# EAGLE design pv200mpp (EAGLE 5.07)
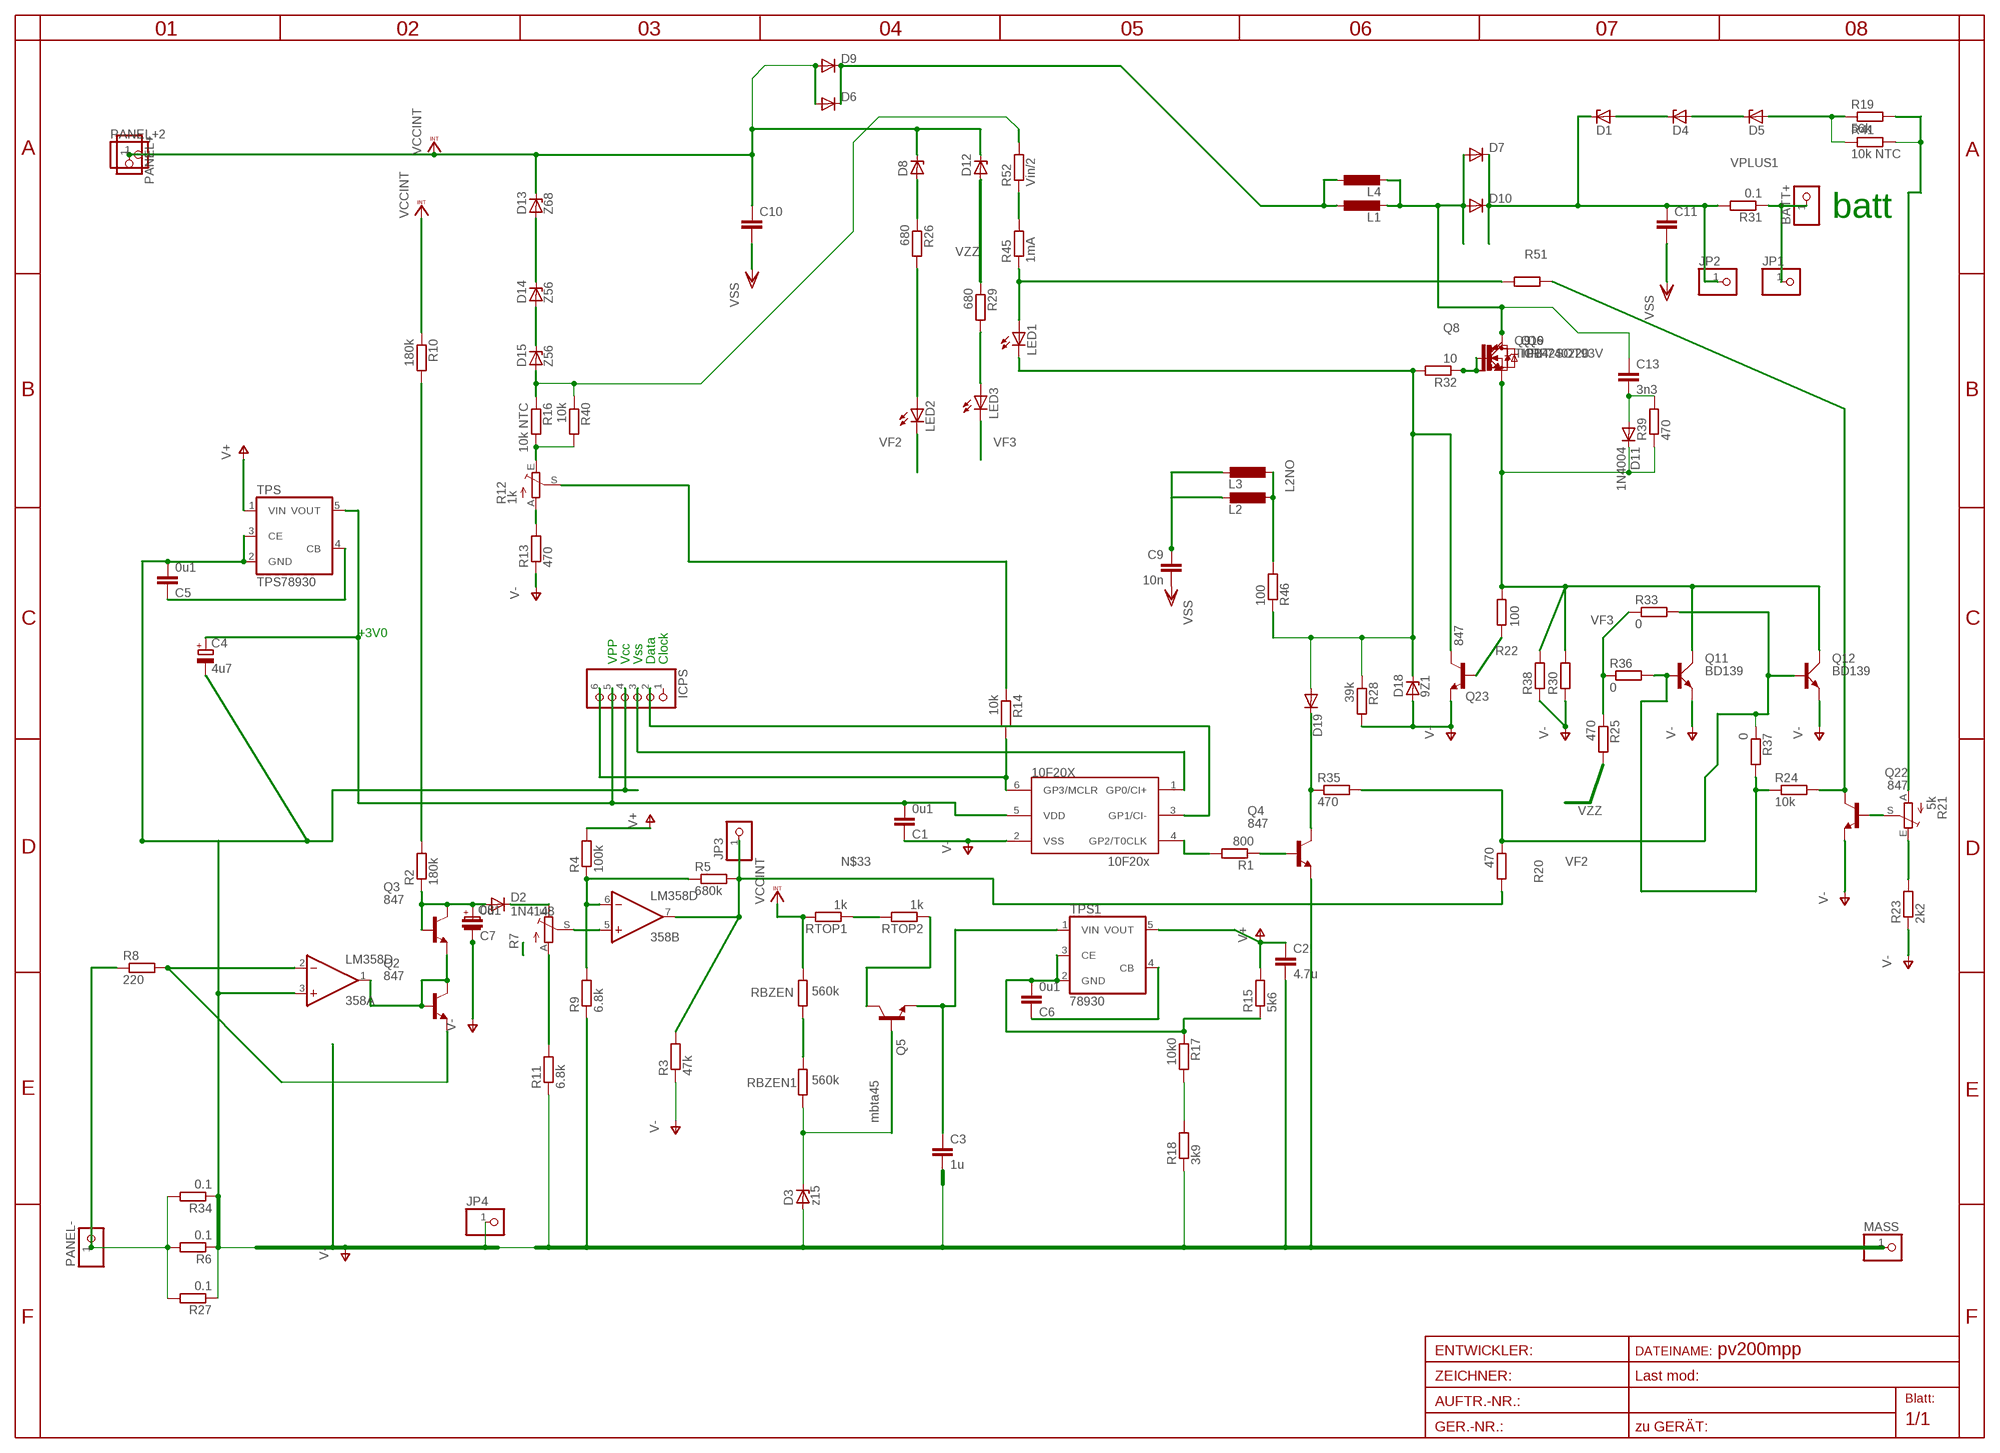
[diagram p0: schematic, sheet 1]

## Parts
10F20X  10F20x  PIC10F204OT  [SOT23-6]
358  LM358D  [SO08]
BATT+  PINHD-1X12MM3  [1X2MM3]
C1  0u1  C-EUC1206  [C1206]
C2  4.7u  C-EUC1206  [C1206]
C3  1u  C-EUC1206  [C1206]
C4  4u7  CPOL-EUSMCA  [SMC_A]
C5  0u1  C-EUC0805  [C0805]
C6  0u1  C-EUC0805  [C0805]
C7  0u1  C-EUC1608  [C1608]
C8  CPOL-EUSMCA  [SMC_A]
C9  10n  C-EUC0805  [C0805]
C10  C-EU075-052X106  [C075-052X106]
C11  C-EU075-052X106  [C075-052X106]
C13  3n3  C-EU050-025X075  [C050-025X075]
D1  ZENER-DIODESOD80C  [SOD80C]
D2  1N4148  DIODE-SOD80C  [SOD80C]
D3  z15  ZENER-DIODESOD80C  [SOD80C]
D4  ZENER-DIODESOD80C  [SOD80C]
D5  ZENER-DIODESOD80C  [SOD80C]
D6  DIODE-SMC  [SMC]
D7  DIODE-SMC  [SMC]
D8  ZENER-DIODESOD80C  [SOD80C]
D9  DIODE-SMC  [SMC]
D10  DIODE-SMC  [SMC]
D11  1N4004  [DO41-10]
D12  ZENER-DIODESOD80C  [SOD80C]
D13  Z68  ZENER-DIODESOD80C  [SOD80C]
D14  Z56  ZENER-DIODESOD80C  [SOD80C]
D15  Z56  ZENER-DIODESOD80C  [SOD80C]
D18  9Z1  ZENER-DIODESOD80C  [SOD80C]
D19  DIODE-MINIMELF  [MINIMELF]
ICPS  PINHD-1X6  [1X06BOX]
JP1  PINHD-1X11MM0  [1X1MM0]
JP2  PINHD-1X11MM0  [1X1MM0]
JP3  PINHD-1X11MM0  [1X1MM0]
JP4  PINHD-1X11MM6  [1X1MM8]
L1  L-EUOPEN6  [OPEN6_3]
L2  L-EUOPEN6  [OPEN6_3]
L3  L-EU0207/12  [0207/12]
L4  L-EU0207/12  [0207/12]
LED1  LEDCHIPLED_1206  [CHIPLED_1206]
LED2  LEDCHIPLED_1206  [CHIPLED_1206]
LED3  LEDCHIPLED_1206  [CHIPLED_1206]
MASS  PINHD-1X12MM3  [1X2MM3]
PANEL+  PINHD-1X11MM0  [1X1MM0]
PANEL+2  PINHD-1X12MM3  [1X2MM3]
PANEL-  PINHD-1X12MM3  [1X2MM3]
Q2  847  BC847ALT1SMD  [SOT23]
Q3  847  BC847ALT1SMD  [SOT23]
Q4  847  BC847ALT1SMD  [SOT23]
Q5  mbta45  BC847ALT1SMD  [SOT23]
Q6  IRF740220  [TO220BV]
Q8  IRG4BC15UD-S  [D2PACK]
Q9  TIP142SOT93V  [SOT93V]
Q11  BD139  [TO126AV]
Q12  BD139  [TO126AV]
Q19  IGBT  N-HEXFET_DPAK-  [TO252]
Q22  847  BC847ASMD  [SOT23]
Q23  847  BC847ASMD  [SOT23]
R1  800  R-EU_R0805  [R0805]
R2  180k  R-EU_0207/15  [0207/15]
R3  47k  R-EU_R0805  [R0805]
R4  100k  R-EU_R1206  [R1206]
R5  680k  R-EU_R0805  [R0805]
R6  0.1  R-EU_R1210  [R1210]
R7  TRIM_EU-S64W  [S64W]
R8  220  R-EU_R0805  [R0805]
R9  6.8k  R-EU_R1206  [R1206]
R10  180k  R-EU_R1206  [R1206]
R11  6.8k  R-EU_R0805  [R0805]
R12  1k  TRIM_EU-S64W  [S64W]
R13  470  R-EU_R0805  [R0805]
R14  10k  R-EU_R0805  [R0805]
R15  5k6  R-EU_R0805  [R0805]
R16  10k NTC  R-EU_0204/2V  [0204V]
R17  10k0  R-EU_R0805  [R0805]
R18  3k9  R-EU_R0805  [R0805]
R19  56k  R-EU_R0805  [R0805]
R20  470  R-EU_R0805  [R0805]
R21  5k  TRIM_EU-S64W  [S64W]
R22  100  R-EU_R0805  [R0805]
R23  2k2  R-EU_R0805  [R0805]
R24  10k  R-EU_R0805  [R0805]
R25  470  R-EU_R1206  [R1206]
R26  680  R-EU_R0805  [R0805]
R27  0.1  R-EU_R3216  [R3216]
R28  39k  R-EU_R0805  [R0805]
R29  680  R-EU_R0805  [R0805]
R30  R-EU_R1210  [R1210]
R31  0.1  R-EU_R1210  [R1210]
R32  10  R-EU_R0805  [R0805]
R33  0  R-EU_R0603  [R0603]
R34  0.1  R-EU_R1210  [R1210]
R35  470  R-EU_R0805  [R0805]
R36  0  R-EU_R0603  [R0603]
R37  0  R-EU_R1206  [R1206]
R38  R-EU_R3216  [R3216]
R39  470  R-EU_0207/10  [0207/10]
R40  10k  R-EU_R0805  [R0805]
R41  10k NTC  R-EU_0204/2V  [0204V]
R45  1mA  R-EU_R1206  [R1206]
R46  100  R-EU_R0805  [R0805]
R51  39k  R-EU_R1206  [R1206]
R52  Vin/2  R-EU_R0805  [R0805]
RBZEN  560k  R-EU_R1206  [R1206]
RBZEN1  560k  R-EU_R1206  [R1206]
RTOP1  1k  R-EU_R1206  [R1206]
RTOP2  1k  R-EU_R1206  [R1206]
TPS  TPS78930  TPS78930SOT23-5  [SOT25]
TPS1  78930  TPS78930SOT23-5  [SOT25]

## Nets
BOOST_EN: D19.C Q4.3(C) R35.1
CB: D3.C Q5.1(B) RBZEN1.2
D1: C13.1 D7.A D10.A L1.2 L4.2 Q6.D Q8.2(C) Q9.C Q19.3(D)
GND1: C6.1 TPS1.4(CB)
IN-: PANEL-.1 R6.2 R8.1 R27.2 R34.2
L1NO: D6.C D9.C L1.1 L4.1
L2DOT: C9.1 L2.2 L3.2
L2NO: L2.1 L3.1 R46.2
N$1: Q11.B R24.1 R36.2 R37.2
N$2: R7.A R11.2
N$3: LED2.A R26.2
N$4: 10F20X.1(GP0/CI+) ICPS.3
N$5: 10F20X.4(GP2/T0CLK) R1.2
N$6: R2.2 R10.2
N$7: 358.1(A:OUT) Q2.1(B) Q2.3(C) Q3.2(E)
N$8: 10F20X.3(GP1/CI-) ICPS.2
N$9: 10F20X.5(VDD) C1.2 C4.+ ICPS.5 TPS.5(VOUT)
N$10: 358.2(A:-IN) Q2.2(E) R8.2
N$11: C5.1 TPS.4(CB)
N$12: C7.2 C8.+ D2.A Q3.1(B) Q3.3(C) R2.1
N$13: D2.C R7.E
N$15: 358.5(B:+IN) R7.S
N$16: Q5.3(C) RTOP2.1
N$17: 358.6(B:-IN) R4.1 R5.1 R9.2
N$18: D15.A R16.1 R40.1 R52.2
N$19: RBZEN1.1 RBZEN.2
N$20: LED1.A R45.1 R51.1
N$21: Q23.1(B) R22.2
N$22: D5.A R19.1 R41.1
N$23: D14.A D15.C
N$24: D13.A D14.C
N$25: R12.E R16.2 R40.2
N$26: R12.A R13.2
N$27: R45.2 R52.1
N$28: R17.2 R18.2
N$29: RTOP1.1 RTOP2.2
N$30: D4.A D5.C
N$31: D1.A D4.C
N$32: R19.2 R21.A R41.2
N$33: 358.7(B:OUT) JP3.1 R3.2 R5.2 R20.2
N$34: R21.E R23.2
N$37: D8.A R26.1
N$38: LED3.A R29.2
N$39: Q4.1(B) R1.1
N$58: Q6.G Q8.1(G) Q9.B Q19.1(G) R32.1
N$71: Q22.3(C) R24.2 R51.2
OUT+: BATT+.1 JP1.1 R31.1
P-: D11.C Q6.S Q8.3(E) Q9.E Q11.C Q12.C Q19.2(S) R22.1 R30.2 R38.2 R39.1
PGATE: D18.C D19.A LED1.C Q23.3(C) R28.1 R32.2 R46.1
PIR: 10F20X.6(GP3/MCLR) ICPS.6 R14.2
PRB1: Q22.1(B) R21.S
SNUB1: C13.2 D11.A R39.2
V15: C3.1 Q5.2(E) TPS1.1(VIN)
V+: C2.1 R4.2 R15.2 TPS1.5(VOUT) TPS.1(VIN)
V-: 10F20X.2(VSS) 358.3(A:+IN) C1.1 C2.2 C3.2 C4.- C5.2 C7.1 C8.- C9.2 C10.2 C11.2 D3.A D18.A ICPS.4 JP4.1 MASS.1 Q4.2(E) Q11.E Q12.E Q22.2(E) Q23.2(E) R3.1 R6.1 R9.1 R11.1 R13.1 R18.1 R23.1 R27.1 R28.2 R30.1 R34.1 R38.1 TPS.2(GND) TPS.3(CE) ; supply symbol labelled VSS
VCCINT: C10.1 D6.A D8.C D9.A D12.C D13.C PANEL+2.1 PANEL+.1 R10.1 RBZEN.1 RTOP1.2
VF2: LED2.C Q12.B R20.1 R33.2 R35.2 R37.1
VF3: LED3.C R25.1 R33.1 R36.1
VINFB: R12.S R14.1
VPLUS1: C11.1 D1.C D7.C D10.C JP2.1 R31.2
VZZ: D12.A R25.2 R29.1
X: C6.2 R15.1 R17.1 TPS1.2(GND) TPS1.3(CE)
Unconnected: ICPS.1

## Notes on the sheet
- batt
- +3V0
- VPP | Vcc | Vss | Data | Clock

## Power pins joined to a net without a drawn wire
V+: 358.8(P:V+)
V-: 358.4(P:V-)

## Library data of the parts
10F20X = microchip-3:PIC10F2*: uPC nW 0,25/0,5k Program Flash memory Comparator
358 = linear:LM358: OP AMP also LM158; LM258; LM2904 Source: http://cache.national.com/ds/LM/LM158.pdf
BATT+ JP1-JP4 MASS PANEL+ PANEL+2 PANEL- = pinhead:PINHD-1X1: PIN HEADER
C1-C3 C5-C7 C9-C11 = rcl:C-EU: CAPACITOR, European symbol
C4 = rcl(2):CPOL-EU: POLARIZED CAPACITOR, European symbol
C8 = rcl:CPOL-EU: POLARIZED CAPACITOR, European symbol
C13 = rcl-2:C-EU: CAPACITOR, European symbol
D1 D3-D5 D8 D12-D15 D18 = diode:ZENER-DIODE: Z-Diode
D2 D6 D7 D9 D10 D19 = diode:DIODE-: DIODE
D11 = diode:1N4004: DIODE
ICPS = pinhead:PINHD-1X6: PIN HEADER
L1-L4 = rcl:L-EU: INDUCTOR, European symbol
LED1-LED3 = led:LED: LED
Q2-Q5 Q22 Q23 = transistor-npn:BC847*: NPN Transistor
Q6 = transistor-power:IRF740: N-CHANNEL MOS FET
Q8 = transistor-power:IRG4BC15UD-: INSULATED GATE BIPOLAR TRANSISTOR WITH ULTRAFAST SOFT RECOVERY DIODE
Q9 = transistor-power:TIP142: NPN DARLINGTON TRANSISTOR
Q11 Q12 = transistor-power:BD139: NPN TRANSISTOR
Q19 = transistor-power:N-HEXFET_?-*: HEXFET® Power MOSFET
R1-R6 R8-R11 R13-R20 R22-R31 R33-R38 R40 R41 RBZEN RBZEN1 RTOP1 RTOP2 = rcl:R-EU_: RESISTOR, European symbol
R7 R12 R21 = pot:TRIM_EU-: POTENTIOMETER
R32 R39 R45 R46 R51 R52 = rcl-2:R-EU_: RESISTOR, European symbol
TPS TPS1 = v-reg:TPS78930

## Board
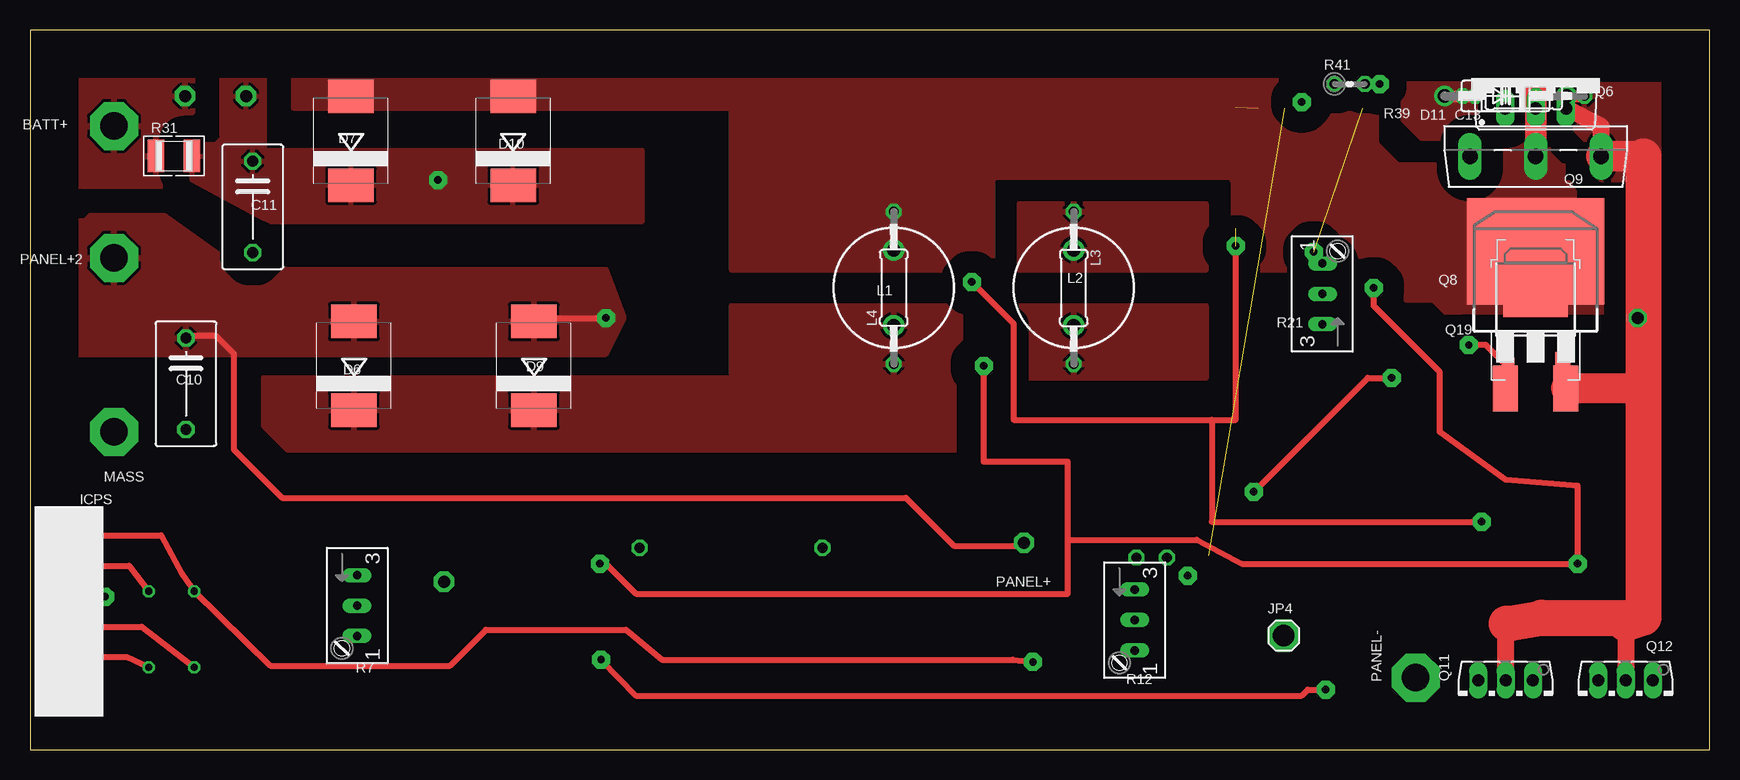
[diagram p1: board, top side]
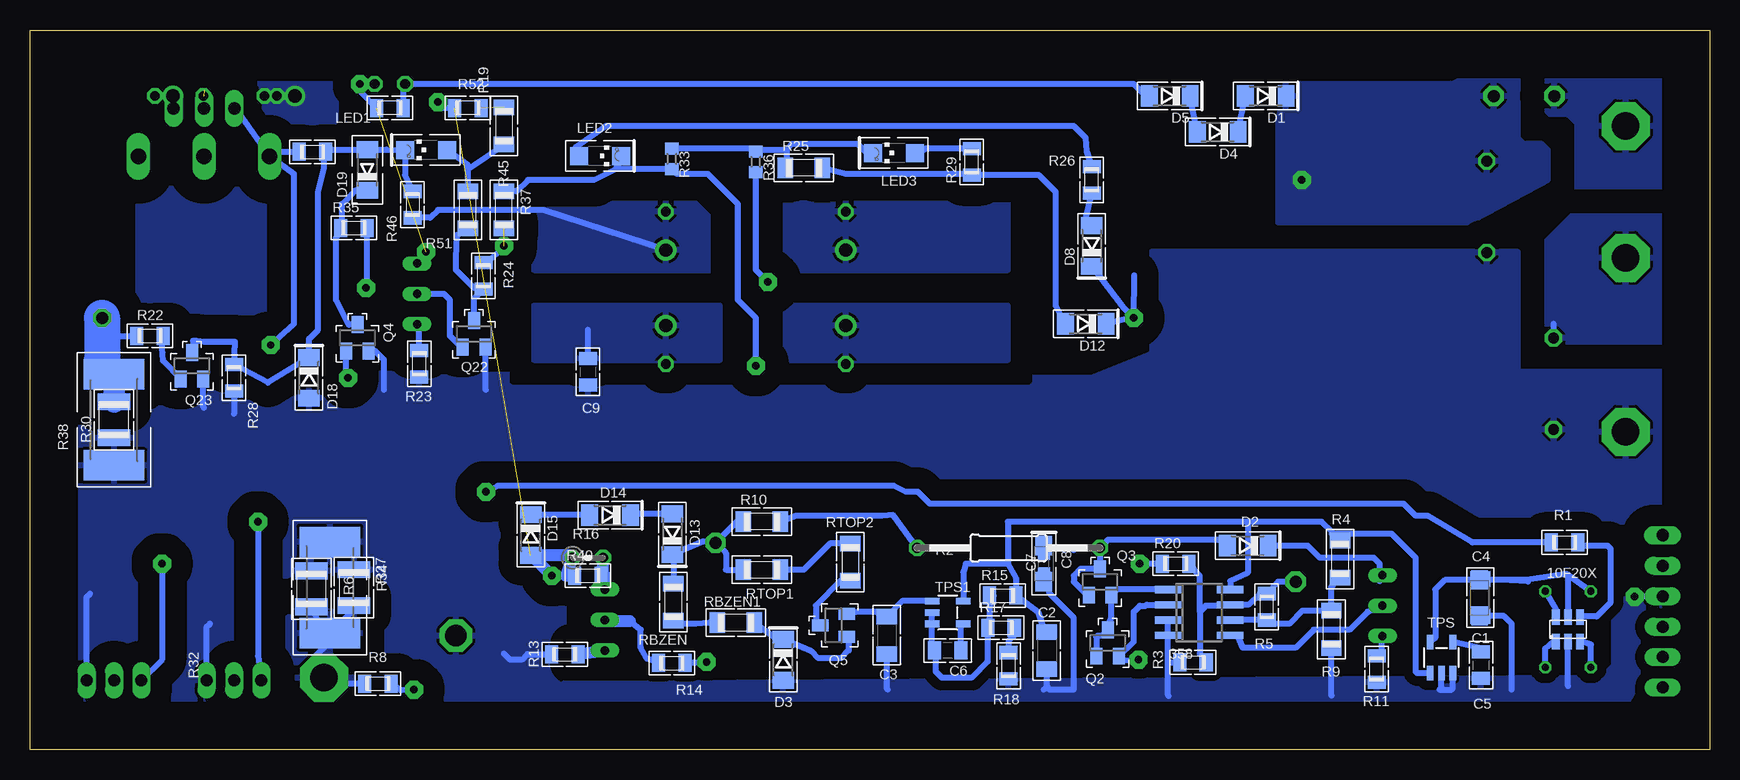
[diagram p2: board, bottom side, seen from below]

Size 140 x 60 mm. Coordinates in mm from the lower left corner, seen from the top.
Outline: 0,0 140,0 140,60 0,60 0,0
Copper layers (1*16): Top 0.035mm / dielectric 1.5mm / Bottom 0.035mm
Design rules "default *": minimum track width 10mil, minimum drill 24mil, track to track 8mil, track to pad 8mil, pad to pad 8mil, via to via 8mil, smd to smd 8mil, copper to edge 4mm, drill to drill 8mil, minimum pad ring 10mil, minimum via ring 8mil, stop-mask expansion 4mil, vias tented up to drill 0mil, thermal gap 10mil

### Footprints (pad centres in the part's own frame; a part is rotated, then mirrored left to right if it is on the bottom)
SOT23-6 = smd 0.635 x 1.27: 1 -1.016,-1.016; 2 0,-1.016; 3 1.016,-1.016; 4 1.016,1.016; 5 0,1.016; 6 -1.016,1.016
SO08 = smd 0.6 x 2.2: 1 -1.905,-2.6; 2 -0.635,-2.6; 3 0.635,-2.6; 4 1.905,-2.6; 5 1.905,2.6; 6 0.635,2.6; 7 -0.635,2.6; 8 -1.905,2.6
1X2MM3 = drill 2.3 pad 4 octagon: 1 0,0
C1206 = smd 1.3 x 1.7: 1 -1.55,0; 2 1.55,0
SMC_A = smd 1.6 x 1.4: + -1.5,0; - 1.5,0
C0805 = smd 1.1 x 1.5: 1 -1.1,0; 2 1.1,0
C1608 = smd 1.1 x 1: 1 -0.85,0; 2 0.85,0
C075-052X106 = drill 0.914 octagon: 1 -3.81,0; 2 3.81,0
C050-025X075 = drill 0.813 octagon: 1 -2.54,0; 2 2.54,0
SOD80C = smd 1.4 x 1.8: A 1.7,0; C -1.7,0
SMC = smd 2.8 x 3.8: A 3.7,0; C -3.7,0
DO41-10 = drill 1.118 round: A 5.08,0; C -5.08,0
MINIMELF = smd 1.4 x 1.8: A 1.7,0; C -1.7,0
1X06BOX = drill 1 long: 1 -6.35,0; 2 -3.81,0; 3 -1.27,0; 4 1.27,0; 5 3.81,0 | drill 1.016 long: 6 6.35,0
1X1MM0 = drill 1 pad 1.676 octagon: 1 0,0
1X1MM8 = drill 1.8 pad 2.54 octagon: 1 0,0
OPEN6_3 = drill 1.1 pad 1.778 round: 1 -3.15,0; 2 3.15,0
0207/12 = drill 0.813 octagon: 1 -6.35,0; 2 6.35,0
CHIPLED_1206 = smd 1.5 x 1.5: A 0,-1.75; C 0,1.75
SOT23 = smd 1 x 1.4: 1 -0.95,-1.1; 2 0.95,-1.1; 3 0,1.1
TO220BV = drill 1.016 long: D 0,-2.54; G -2.54,-2.54; S 2.54,-2.54
D2PACK = smd 2.083 x 3.81: 1 -2.54,-8.89; 3 2.54,-8.89 | smd 11.43 x 8.89: 2 0,2.54
SOT93V = drill 1.3 pad 1.676 long: B -5.461,-2.54; C 0,-2.54; E 5.461,-2.54
TO126AV = drill 1 pad 1.27 long: B 2.286,-1.27; C 0,-1.27; E -2.286,-1.27
TO252 = smd 1 x 1.6: 1 -2.28,-3.53 | smd 1.27 x 2.54: 2 2.28,-3.53 | smd 5.4 x 6.2: 3 0,3.77
R0805 = smd 1.1 x 1.5: 1 -1.1,0; 2 1.1,0
0207/15 = drill 0.813 octagon: 1 -7.62,0; 2 7.62,0
R1206 = smd 1.3 x 1.7: 1 -1.55,0; 2 1.55,0
R1210 = smd 1.4 x 2.7: 1 -1.5,0; 2 1.5,0
S64W = drill 0.7 long: A 2.54,1.27; E -2.54,1.27; S 0,1.27
0204V = drill 0.813 octagon: 1 -1.27,0; 2 1.27,0
R3216 = smd 2.54 x 5.08: 1 -3.81,0; 2 3.81,0
R0603 = smd 1 x 1.1: 1 -0.85,0; 2 0.85,0
0207/10 = drill 0.813 octagon: 1 -5.08,0; 2 5.08,0
SOT25 = smd 0.55 x 1.2: 1 -0.95,-1.3; 2 0,-1.3; 3 0.95,-1.3; 4 0.95,1.3; 5 -0.95,1.3

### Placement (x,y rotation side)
10F20X  11.79,10.03 0 bottom
358  42.55,11.43 270 bottom
BATT+  7,52 0 top
C1  19.11,12.66 90 bottom
C2  55.24,8.26 270 bottom
C3  68.58,9.53 270 bottom
C4  19.18,12.63 270 bottom
C5  19.05,7.04 270 bottom
C6  63.5,8.26 180 bottom
C7  55.5,15.5 90 bottom
C8  55.5,15.5 270 bottom
C9  93.5,31.5 270 bottom
C10  13,30.5 270 top
C11  18.57,45.25 270 top
C13  123,54.5 180 top
D1  37,54.5 180 bottom
D2  38.5,17 180 bottom
D3  77.22,7.48 270 bottom
D4  41,51.5 180 bottom
D5  45,54.5 180 bottom
D6  27,32 90 top
D7  26.77,50.75 90 top
D8  51.5,42 90 bottom
D9  42,32 90 top
D10  40.29,50.75 90 top
D11  123,54.5 180 top
D12  52,35.5 180 bottom
D13  86.45,17.96 90 bottom
D14  91.65,19.55 180 bottom
D15  98.27,17.88 270 bottom
D18  116.75,31 270 bottom
D19  111.88,48.33 90 bottom
ICPS  3.9,11.52 90 top
JP1  12.92,54.5 0 top
JP2  18,54.5 0 top
JP3  34.5,14 0 top
JP4  104.5,9.5 0 top
L1  72,38.5 90 top
L2  87,38.5 270 top
L3  87,38.5 270 top
L4  72,38.5 90 top
LED1  107,50 90 bottom
LED2  92.5,49.5 270 bottom
LED3  68,49.75 90 bottom
MASS  7,26.5 0 top
PANEL+  82.86,17.24 0 top
PANEL+2  7,41 0 top
PANEL-  115.5,6 90 top
Q2  50.16,8.89 0 bottom
Q3  50.8,13.97 0 bottom
Q4  112.7,34.33 0 bottom
Q5  73.03,10.35 90 bottom
Q6  125.5,56 0 top
Q8  125.5,39 0 top
Q9  125.5,52 0 top
Q11  123,4.5 180 top
Q12  133,4.5 180 top
Q19  125.5,35.4 0 top
Q22  102.99,34.66 0 bottom
Q23  126.5,32 0 bottom
R1  12.08,17.27 0 bottom
R2  58.44,16.81 180 bottom
R3  43.05,7.27 0 bottom
R4  30.8,15.88 90 bottom
R5  36.9,11.9 90 bottom
R6  116.56,13.39 270 bottom
R7  26,12 270 top
R8  111,5.5 0 bottom
R9  31.52,10.03 90 bottom
R10  79,19 0 bottom
R11  27.75,6.71 90 bottom
R12  90.81,10.79 270 top
R13  95.42,7.94 0 bottom
R14  86.5,7.21 0 bottom
R15  58.92,12.84 0 bottom
R16  93.5,16 0 bottom
R17  59.05,10.16 0 bottom
R18  58.42,6.99 90 bottom
R19  110,53.5 180 bottom
R20  44.5,15.5 0 bottom
R21  109,38 90 top
R22  130,34.5 0 bottom
R23  107.55,32.16 90 bottom
R24  102.2,39.5 270 bottom
R25  75.5,48.5 0 bottom
R26  51.5,47.5 90 bottom
R27  115,13.5 270 bottom
R28  123,31 270 bottom
R29  61.5,49 90 bottom
R30  133,27.5 90 bottom
R31  12,49.5 0 top
R32  116.45,49.84 0 bottom
R33  86.5,49.25 270 bottom
R34  113,13.5 270 bottom
R35  113,43.5 0 bottom
R36  79.5,49 270 bottom
R37  100.5,45 270 bottom
R38  133,27.5 90 bottom
R39  124.5,54.5 180 top
R40  93.5,14.5 0 bottom
R41  110,55.5 0 top
R45  100.5,52 90 bottom
R46  108.11,45.44 270 bottom
R51  103.5,45 270 bottom
R52  103.5,53.5 180 bottom
RBZEN  86.36,12.29 270 bottom
RBZEN1  81.16,10.57 0 bottom
RTOP1  79,15 180 bottom
RTOP2  71.62,15.62 90 bottom
TPS  22.35,7.67 0 bottom
TPS1  63.5,11.43 270 bottom

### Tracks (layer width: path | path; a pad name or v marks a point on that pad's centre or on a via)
BOOST_EN
  Bottom 0.5: D19.C 112.87,46.63 114,45.5 114,44.1 R35.1 114.5,42.6 114.5,37.5 113.43,35.43 Q4.3
CB
  Bottom 0.5: Q5.1 71.75,9.23 71.75,8.26 72.39,7.62 74.3,7.62 74.85,8.18 D3.C 77.72,9.18 RBZEN1.2
D1  (1 unrouted)
  Top 1.8: Q9.C Q6.D 125.5,55
  pour Bottom (isolate 2, rank 2): 58.5,46 78,46 78,40 58.5,40
  pour Top (isolate 1.8, rank 4, no thermals): 22,53.5 22,58 128.5,58.5 137,36.5 118,36.5 117,37.5 107.5,37.5 108,40 58.5,40 58.5,53.5
DQ18
  pour Bottom (isolate 2): 119,51 130,51 131,49.5 131,36.5 119,36.5 118,37.5
GND1
  Bottom 0.5: C6.1 62.4,10.28 TPS1.4
IN-
  Bottom 0.5: R6.2 115.06,8.95 116.33,7.68 PANEL-.1 115.5,5.5 R8.1 | R34.2 113,11.69 R27.2
  pour Bottom (isolate 2): 119,2 114,2 112.5,3.5 112.5,11.5 118,11.5 118.5,11
L1NO
  pour Top (isolate 2, rank 3): 19.5,31 58.5,31 58.5,37 77.5,37 77.5,25 21.5,25 19.5,27
  pour Bottom (isolate 2): 58.5,37 78,37 78,32.5 58.5,32.5
L2DOT
  Bottom 0.5: C9.1 93.5,35
  pour Bottom (isolate 1): 82.5,37 98,37 98,32.5 82.5,32.5
  pour Top (isolate 1): 82.5,37 98,37 98,31 82.5,31
L2NO
  Bottom 0.5: R46.2 106.66,44.34 106,45 97.24,45 L2.1
  pour Bottom (isolate 2): 82.5,40 82.5,45.5 98,45.5 98,40
  pour Top (isolate 2): 82.5,40 82.5,45.5 98,45.5 98,40
N$1  (via drill 0.6 pad 1.5)  (1 unrouted)
  Top 0.5: v100.5,42 100.5,27.5 98.5,27.5 | v78.5,39 82,35.5 82,27.5 98.5,27.5 | v121,19 98.5,19 98.5,27.5
  Bottom 0.5: R24.1 101.9,40.6 v100.5,42 | Q11.B 121,7.79 v121,19 | v78.5,39 79.5,40 R36.2
N$2
  Bottom 0.5: R7.A 27.3,8.26 R11.2
N$3
  Bottom 0.5: R26.2 51.9,49.9 52,51 53,52 92,52 94.5,50.25 LED2.A
N$4  (via drill 0.6)
  Top 0.5: ICPS.3 9.3,10.25 v13.7,6.85
  Bottom 0.5: v13.7,6.85 13.7,8.4 12.99,9.01 10F20X.1
N$5
  Bottom 0.5: 10F20X.4 10.72,11.1 9.4,11.1 8.24,12.26 8.24,16.74 8.5,17 10.71,17 R1.2
N$6
  Bottom 0.5: R2.2 68.06,19.56 69,19.5 76.14,19.5 R10.2
N$7
  Bottom 0.5: 358.1 49.38,13.34 Q3.2 49.9,12.42 49.9,10.9 50.16,10.34 Q2.3 50.66,9.5 51,9.5 51.12,9.38 Q2.1
N$8  (via drill 0.6)
  Top 0.5: ICPS.2 8.03,7.71 v9.89,6.85
  Bottom 0.5: v9.89,6.85 9.89,8.76 10F20X.3
N$9  (via drill 0.6)
  Top 0.5: ICPS.5 8.26,15.33 v9.89,13.2
  Bottom 0.5: 15.24,14.13 11.86,14.63 11.75,14.52 | 15.24,14.13 C4.+ 22.06,14.13 22.86,13.34 22.86,9.3 TPS.5 | v9.89,13.2 11.7,14.47 11.75,14.52 | 10F20X.5 11.79,14.47 11.75,14.52 | C1.2 15.11,14 15.24,14.13
N$10  (via drill 0.6 pad 1.5)
  Top 0.5: v108,5 106.5,5 106,4.5 50.5,4.5 v47.6,7.5
  Bottom 0.5: 358.2 46.94,12.06 47,12 47.5,12 48,11.5 48,9 Q2.2 49.1,7.41 v47.6,7.5 | R8.2 109.08,4.92 v108,5
N$11
  Bottom 0.5: TPS.4 19.25,8.47 C5.1
N$12
  Bottom 0.5: D2.A 41,17.5 50.13,17.5 R2.1 | R2.1 52.82,16.78 53.12,16.73 | Q3.1 51.87,12.87 53,14 53,14.5 52.43,15.07 Q3.3 50.82,15.09 R2.1 | 53.12,16.73 53,16.62 | C7.2 C8.+ 55.23,16.73 53.12,16.73
N$13
  Bottom 0.5: D2.C 33.49,16.99 32.5,16 28,16 27.5,15.5 27.5,14.03 R7.E
N$15
  Bottom 0.5: 358.5 39.33,9.53 38.9,8.5 34.5,8.5 33,10 30,10 28.5,11.5 27.09,12 R7.S
N$16
  Bottom 0.5: RTOP2.1 72.43,14.07 74.5,12 74.5,10.73 Q5.3
N$17
  Bottom 0.5: R4.1 31.52,13.55 R9.2 33.92,11.57 35,10.5 36.59,10.5 R5.1 37.91,10.79 358.6
N$18  (via drill 0.6 pad 1.5)  (1 unrouted)
  Top 0.5: v96.5,14.5 96.5,15
  Bottom 0.5: R16.1 94.66,16.18 | R52.2 106,53.5 v106,54 | D15.A 98.18,16.18
  Bottom 1: 94.66,16.18 D15.A | R40.1 95.32,14.5 R16.1 | 98.18,16.18 v96.5,14.5
N$19
  Bottom 0.5: RBZEN1.1 83.37,10.57 84.5,10.5 85.61,10.5 RBZEN.2
N$20
  Bottom 0.5: R51.1 103.5,48.5 | 103.5,48.5 103.5,48.75 LED1.A | R45.1 103.45,48.45 103.5,48.5
N$21
  Bottom 0.5: Q23.1 128.9,32.4 129,33.5 129,34.1 R22.2
N$22
  Bottom 0.5: D5.A 47,54.5 48,55.5 R41.1 108.9,55.33 R19.1
N$23
  Bottom 0.5: D14.A 98.23,19.55 D15.C
N$24
  Bottom 0.5: D13.A 89.84,19.66 D14.C
N$25
  Bottom 0.5: R12.E 92.25,13.76 | R40.2 92.08,14.5
  Bottom 1: 92.25,13.76 R16.2 | 92.08,14.5 R12.E
N$26
  Bottom 0.5: R12.A 92.94,8.12
  Bottom 1: 92.94,8.12 R13.2
N$27  (1 unrouted)
N$28
  Bottom 0.5: R18.2 58.42,9.08 58,9.5 58,10.12 R17.2
N$29
  Bottom 0.5: RTOP1.1 75.52,14.98 73.33,17.17 RTOP2.2
N$30
  Bottom 0.5: D4.A D5.C
N$31
  Bottom 0.5: D4.C D1.A
N$32  (via drill 0.6 pad 1.5)  (1 unrouted)
  Top 0.5: R41.2 v112.5,55.5
  Bottom 0.5: v112.5,55.5 112.5,54.9 R19.2 | R21.A 107.73,40.77 v107,41.5
N$33
  Bottom 0.5: R3.2 42.05,7.54 42.5,8 42.5,11.5 | 42.5,11.5 42,12 40.01,12 358.7 38.44,12.06 37.5,13 R5.2 35.95,14 JP3.1 | 42.5,11.5 42.5,14.5 43,15 43,15.1 R20.2
N$34
  Bottom 0.5: R23.2 107.55,35.27 R21.E
N$37
  Bottom 0.5: R26.1 52,44.3 D8.A
N$38
  Bottom 0.5: R29.2 65.4,50.1 65.5,50 LED3.A
N$39  (via drill 0.6 pad 1.5)
  Top 0.5: v102,21.5 111.5,31 v113.5,31
  Bottom 0.5: R1.1 19.77,17.27 23.5,19.5 24.5,19.5 25.5,20.5 65,20.5 66,21.5 67,21.5 68,22 101,22 v102,21.5 | Q4.1 113.66,31.66 v113.5,31
N$58  (via drill 0.6 pad 1.5)
  Top 0.406: Q9.B 119.46,49.46 | Q8.1 122.96,31.61 Q19.1
  Top 0.5: v119.93,33.74 121.35,33.74 Q19.1
  Bottom 0.5: Q6.G 122.54,53.04 Q9.B | v119.93,33.74 118,35.5 118,48 Q9.B | R32.1 119.66,49.84 Q9.B
N$71
  Bottom 0.5: Q22.3 102.99,37.61 R24.2 102.3,38.5 103,38.5 104.5,40 104.5,41 104.4,42.9 R51.2
OUT+
  pour Bottom (isolate 2, rank 2): 0.5,58.5 14,58.5 14,48 12,47 0.5,47
  pour Top (isolate 2, rank 2): 0.5,58.5 14,58.5 14,48 12,47 0.5,47
P-  (via drill 1 pad 1.5)
  Top 0.406: 123.1,10.5 123.1,10 123,10 | 128.04,30 Q8.3 127.78,30.37 Q19.2 | 134.5,36 v134,36
  Top 1: R39.1 D11.C 128.04,54.5 Q6.S
  Top 1.4: 133,10.5 Q12.C | Q11.C 123,10 | Q6.S 130.96,51.96 Q9.E
  Top 2.5: 134.5,30.11 Q8.3
  Top 2.54: 134.5,49.46 Q9.E
  Top 3: 123.1,10.5 126,11 134.5,11 | 134.5,11 133,10.5 | 134.5,11 134.5,30.11 134.5,36 134.5,49.46
  Bottom 0.5: v134,36 134,35 133,34.5 R22.1 | R38.2 134.31,31.81 134,32.5
  Bottom 1.8: R38.2 R30.2
  Bottom 3: v134,36 134,32.5
  pour Top: 127.5,55.5 136.5,55.5 136.5,48 136,47.5 131,47.5 130,48.5 130,50.5 129,51.5 128,52.5
PGATE
  Bottom 0.5: Q23.3 126.4,34.1 125.5,34 122.9,34 R28.1 120.15,30.6 D18.C 116.75,34.25 116,35 116,46.5 115.5,48.5 115.5,49.2 R32.2 115.17,50.03 D19.A 110.28,50.03 LED1.C 108.75,47.9 R46.1
PIR  (via drill 0.6, 0.6 pad 1.5)
  Top 0.5: v83.6,7.3 81.92,7.48 52.67,7.48 49.67,10 38,10 35,7 20.04,7 v13.7,13.2 12.7,14.61 10.94,17.87 ICPS.6
  Bottom 0.5: 10F20X.6 12.81,11.68 v13.7,13.2 | R14.2 84.58,7.21 v83.6,7.3
PRB1
  Bottom 0.5: Q22.1 104.06,33.56 105,34.5 105,37.5 105.5,38 R21.S
SNUB1
  Top 1: D11.A R39.2 C13.2
  pour Bottom (isolate 1.5, no thermals): 114.5,55.5 122,55.5 122,52.5 120.5,51 116,51 114.5,52.5
  pour Top (isolate 1.5, no thermals): 114.5,55.5 122,55.5 122,52.5 120.5,51 116,51 114.5,52.5
V15
  Bottom 0.5: TPS1.1 67.28,12.38 C3.1 69.5,11.5 71,11.5 71.7,11.3 Q5.2
V+
  Bottom 0.5: TPS.1 24.38,6.38 24.5,6.5 24.5,16 26.5,18 31.5,18 31.5,18.18 | 31.5,18.18 R4.2 | 38.5,19 32.32,19 31.5,18.18 | 38.5,19 58.5,19 58.5,15.5 | C2.1 55.24,9.74 55.5,10 56,11.5 R15.2 57.82,14.32 58.5,15.5 | TPS1.5 62.2,14.8 62,15.5 58.5,15.5 | 358.8 39.95,14.05 38.5,14.75 38.5,19
V-  (via drill 0.6 pad 1.5)
  Top 0.5: ICPS.4 5.21,12.29 v6.25,12.75
  Bottom 0.5: 11.79,5.31 10F20X.2 | 45.15,7.27 45.15,4.5 45.09,4.45 | 358.3 358.4 45.15,7.27 | v6.25,12.75 5.54,12.75 ICPS.4 | R9.1 31.52,4.53 31.5,4.5 | C3.2 68.58,5.08 68.5,5 | 55.24,5.25 C2.2 | 55.24,5.25 55.5,5 | R13.1 98.56,7.94 99,7.5 100,7.5 100.5,8 | Q12.E 135.29,12.71 135,13 | Q11.E 125.29,10.21 125,10.5 | TPS.3 21.4,5.1 21.5,5 22.5,5 22.35,5.15 TPS.2 | 55.24,5.25 54.99,5 53,5 53,11 55,13 C7.1 C8.- | 45.15,7.27 R3.1 | Q22.2 102.04,30.04 102,30 | Q4.2 111.23,33.23 110.5,32.5 110.5,30 | 16.5,5 16.5,10.5 17.14,11.13 C4.- 19.16,11.12 C1.1 | Q23.2 125.55,28.55 125.5,28.5 | R28.2 123,28
  pour Bottom (isolate 1.8, rank 2): 95.5,2.5 95.5,19 2.5,19 2.5,31.5 16,31.5 16,41.5 46.5,41.5 46.5,33 51.5,31 139,31.5 139.22,2
  pour Bottom (isolate 0.813): 2.5,13 7.5,12.5 8,12 8,7 9,6 95.5,5.5 96.5,4.5 96.5,3.5 95,2 8,2 6,5.5 6,9.5
VCCINT  (via drill 0.6 pad 1.5)
  Top 0.5: v48,36 42.3,36 D9.A | PANEL+.1 82.62,17 77,17 73,21 21,21 17,25 17,33 15.5,34.5 13.19,34.5 C10.1
  Bottom 0.5: PANEL+.1 83.86,17.34 D13.C 86.36,16.16 RBZEN.1 | C10.1 13,35.5 | PANEL+.1 82,16.38 82,15 RTOP1.2 | PANEL+.1 81.1,19 R10.1 | v48,36 47.95,39.55 | D8.C 48.8,36.8 v48,36 | v48,36 48.3,36 D12.C
  pour Top (isolate 2, rank 3): 48,33 49.5,36 48,40 17.5,40 10.5,45 5.5,45 4.5,44 3,44.5 3,33
  pour Bottom (isolate 2, rank 3): 2,45 11,45 15,41 15,34 13.5,33 2,33
VF2  (via drill 0.6 pad 1.5)
  Top 0.5: v47.5,15.5 48,15.5 50.5,13 86.5,13 86.5,17.5 | v112,38.5 112,37 117.5,31.5 117.5,26.5 123,22.5 129,22 v129,15.5 101,15.5 97.25,17.5 86.5,17.5 | v79.5,32 79.5,24 86.5,24 86.5,17.5
  Bottom 0.5: R20.1 v47.5,15.5 | Q12.B 130.71,5.79 129,7.5 v129,15.5 | R35.2 111.9,39.1 v112,38.5 | v79.5,32 79.5,36 81,37.5 81,45.5 83.5,48 86.1,48 R33.2 91.15,48.4 LED2.C 91,49.25 91,48.5 93,47.5 98.5,47.5 99.45,46.55 R37.1
VF3
  Bottom 0.5: LED3.C 70.25,49.75 71,50.5 76.5,50.5 76.95,50 | R33.1 79.75,50.1 R36.1 79.35,50 76.95,50 | 76.95,50 76.95,48.6 R25.1
VINFB
  Bottom 0.5: R14.1 88.59,7.59 89.1,8.5 89.1,10 90,10.7 | 91.87,10.7 R12.S
  Bottom 1: 90,10.7 91.87,10.7
VPLUS1  (via drill 0.6 pad 1.5)
  other vias: 34,47.5
  pour Top (isolate 2): 16,56 19.5,56.5 19.5,50 51,50 51,44 20,44 13.5,47.5 13.5,50 14,50.5 15.5,50.5 16,51
  pour Bottom (isolate 2): 16,56 19.5,56.5 21.5,55.5 36,55.5 36,44 20,44 13.5,47.5 13.5,50 14,50.5 15.5,50.5 16,51
VZZ
  Bottom 0.5: D12.A 54.5,37 54.5,42.5 54.5,43 54.5,46.5 55.9,47.9 R29.1 61.6,48 72,48 R25.2
X
  Bottom 0.5: R15.1 59.66,12.84 60,12 60,11.01 R17.1 60.16,7.34 61.5,6 64,6 64.5,6.5 64.5,8.15 C6.2 64.8,8.46 TPS1.3 TPS1.2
